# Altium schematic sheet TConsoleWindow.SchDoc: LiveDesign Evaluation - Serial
size A3; Organization: Altium Limited; Address1: L3, 12a Rodborough Rd; Address2: Frenchs Forest; Address3: NSW; Address4: Australia 2086; DocumentNumber: 4; SheetNumber: 4; SheetTotal: 7
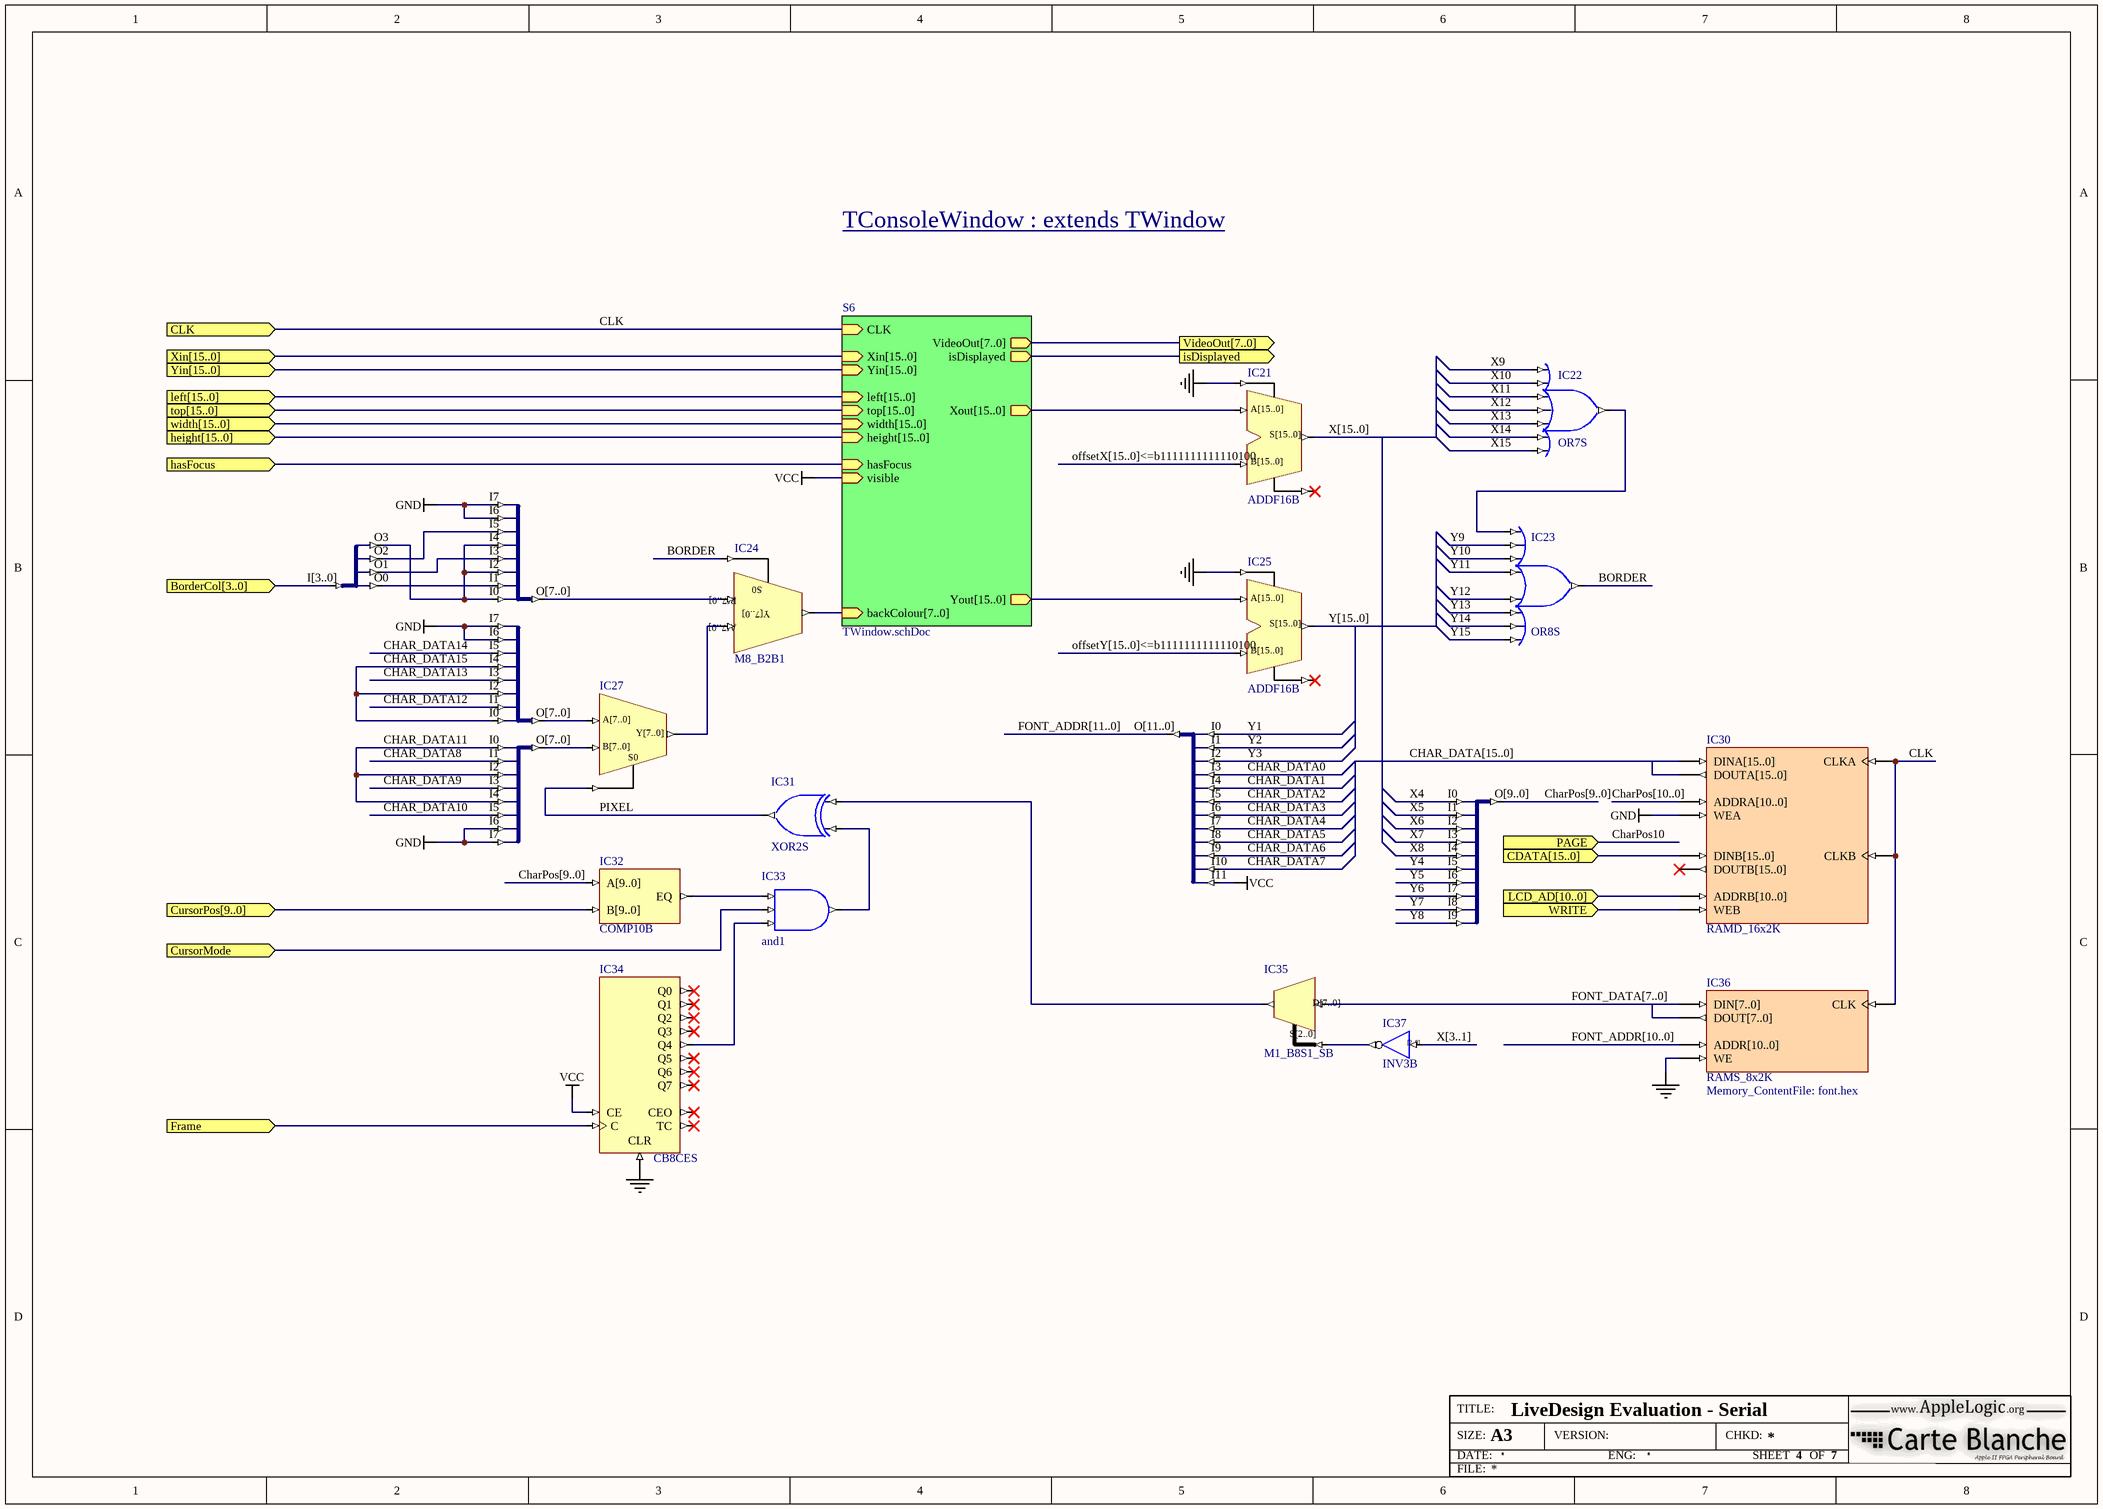
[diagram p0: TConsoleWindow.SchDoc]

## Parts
IC21  ADDF16B
IC22  OR7S
IC23  OR8S
IC24  M8_B2B1
IC25  ADDF16B
IC26  J8S_8B  (value not drawn)
IC27  M8_B2B1  (value not drawn)
IC28  J8S_8B  (value not drawn)
IC29  J8S_8B  (value not drawn)
IC30  RAMD_16x2K
IC31  XOR2S
IC32  COMP10B
IC33  and1
IC34  CB8CES
IC35  M1_B8S1_SB
IC36  RAMS_8x2K  Memory_ContentFile: font.hex
IC37  INV3B
U21  J4B_4S  (value not drawn)
U24  J10S_10B  (value not drawn)
U27  J12S_12B  (value not drawn)

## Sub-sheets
S6 = TWindow.schDoc: CLK (in), VideoOut[7..0] (out), Xin[15..0] (in), Yin[15..0] (in), top[15..0] (in), width[15..0] (in), height[15..0] (in), left[15..0] (in), Xout[15..0] (out), Yout[15..0] (out), backColour[7..0] (in), isDisplayed (out), visible (in), hasFocus (in)

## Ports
BorderCol[3..0] (in), CDATA[15..0] (in), CLK (in), CursorMode (in), CursorPos[9..0] (in), Frame (in), hasFocus (in), height[15..0] (in), isDisplayed (out), LCD_AD[10..0] (in), left[15..0] (in), PAGE (in), top[15..0] (in), VideoOut[7..0] (out), width[15..0] (in), WRITE (in), Xin[15..0] (in), Yin[15..0] (in)

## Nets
GND: IC21.CI IC25.CI IC26.I6 IC26.I7 IC28.I6 IC28.I7 IC29.I6 IC29.I7 IC30.WEA IC34.CLR IC36.WE
VCC: IC34.CE U27.I11 ; sheet S6/visible
BORDER: IC23.O IC24.S0
CHAR_DATA0: U27.I3
CHAR_DATA1: U27.I4
CHAR_DATA2: U27.I5
CHAR_DATA3: U27.I6
CHAR_DATA4: U27.I7
CHAR_DATA5: U27.I8
CHAR_DATA6: U27.I9
CHAR_DATA7: U27.I10
CHAR_DATA8: IC29.I1
CHAR_DATA9: IC29.I3
CHAR_DATA10: IC29.I5
CHAR_DATA11: IC29.I0 IC29.I2 IC29.I4
CHAR_DATA12: IC28.I1
CHAR_DATA13: IC28.I3
CHAR_DATA14: IC28.I5
CHAR_DATA15: IC28.I0 IC28.I2 IC28.I4
CLK: IC30.CLKA IC30.CLKB IC36.CLK ; port CLK, sheet S6/CLK
CursorMode: IC33.I1 ; port CursorMode
Frame: IC34.C ; port Frame
hasFocus: port hasFocus, sheet S6/hasFocus
isDisplayed: port isDisplayed, sheet S6/isDisplayed
PIXEL: IC27.S0 IC31.O
WRITE: IC30.WEB ; port WRITE
X4: U24.I0
X5: U24.I1
X6: U24.I2
X7: U24.I3
X8: U24.I4
X9: IC22.I0
X10: IC22.I1
X11: IC22.I2
X12: IC22.I3
X13: IC22.I4
X14: IC22.I5
X15: IC22.I6
Y1: U27.I0
Y2: U27.I1
Y3: U27.I2
Y4: U24.I5
Y5: U24.I6
Y6: U24.I7
Y7: U24.I8
Y8: U24.I9
Y9: IC23.I1
Y10: IC23.I2
Y11: IC23.I3
Y12: IC23.I4
Y13: IC23.I5
Y14: IC23.I6
Y15: IC23.I7
NetIC22_O: IC22.O IC23.I0
NetIC26_I0: IC26.I0 IC26.I2 IC26.I4 U21.O3
NetIC26_I1: IC26.I1 U21.O0
NetIC26_I3: IC26.I3 U21.O1
NetIC26_I5: IC26.I5 U21.O2
NetIC31_I0: IC31.I0 IC35.O
NetIC31_I1: IC31.I1 IC33.O
NetIC32_EQ: IC32.EQ IC33.I0
NetIC33_I2: IC33.I2 IC34.Q4

Not connected (* = marked no-connect by the designer): IC21 A[15..0] B[15..0] CO* S[15..0]; IC24 A[7..0] B[7..0] Y[7..0]; IC25 A[15..0] B[15..0] CO* S[15..0]; IC26 O[7..0]; IC27 A[7..0] B[7..0] Y[7..0]; IC28 O[7..0]; IC29 O[7..0]; IC30 ADDRA[10..0] ADDRB[10..0] DINA[15..0] DINB[15..0] DOUTA[15..0] DOUTB[15..0]*; IC32 A[9..0] B[9..0]; IC34 CEO* Q0* Q1* Q2* Q3* Q5* Q6* Q7* TC*; IC35 D[7..0] S[2..0]; IC36 ADDR[10..0] DIN[7..0] DOUT[7..0]; IC37 I[2..0] O[2..0]; U21 I[3..0]; U24 O[9..0]; U27 O[11..0]

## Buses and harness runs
bus CHAR_DATA[15..0]
bus CharPos[9..0]
bus CharPos[10..0]
bus FONT_ADDR[10..0]
bus FONT_ADDR[11..0]
bus FONT_DATA[7..0]
bus offsetX[15..0]<=b1111111111110100
bus offsetY[15..0]<=b1111111111110100
bus port height[15..0] = sheet S6/height[15..0]
bus port left[15..0] = sheet S6/left[15..0]
bus port top[15..0] = sheet S6/top[15..0]
bus port VideoOut[7..0] = sheet S6/VideoOut[7..0]
bus port width[15..0] = sheet S6/width[15..0]
bus port Xin[15..0] = sheet S6/Xin[15..0]
bus port Yin[15..0] = sheet S6/Yin[15..0]
bus X[3..1]
bus X[15..0]
bus Y[15..0]

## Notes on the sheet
- TConsoleWindow : extends TWindow

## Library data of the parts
IC21 IC25 = ADDF16B: 16-Bit Cascadable Unsigned Binary Full Adder, Bus Version; ArchiveName: GENERIC; VHDLIB_SIM: GENERIC_LIB
IC22 = OR7S: 7-Input OR Gate, Single Pin Version; Xilinx Equivalent: OR7; ArchiveName: GENERIC; VHDLIB_SIM: GENERIC_LIB
IC23 = OR8S: 8-Input OR Gate, Single Pin Version; ArchiveName: GENERIC; VHDLIB_SIM: GENERIC_LIB; Xilinx Equivalent: OR8
IC24 IC27 = M8_B2B1: 2x8-Bit Bus to 1x8-Bit Bus Multiplexer; ArchiveName: GENERIC; VHDLIB_SIM: GENERIC_LIB
IC26 IC28 IC29 = J8S_8B: 8 Single pin inputs to single 8-Bit output bus; ArchiveName: GENERIC; VHDLIB_SIM: GENERIC_LIB
IC30 = RAMD_16x2K: Dual Port RAM; Memory_DepthA: 2048; Memory_Type: RAM_DualPortBlock; Memory_WidthA: 16; Memory_ClockEdge: Rising; Nexus_Core: Memory_Program; Memory_EnablePin: False
IC31 = XOR2S: 2-Input Exclusive-OR Gate, Single Pin Version; ArchiveName: GENERIC; VHDLIB_SIM: GENERIC_LIB; Xilinx Equivalent: XOR2
IC32 = COMP10B: 10-Bit Identity Comparator, Bus Version; ArchiveName: GENERIC; VHDLIB_SIM: GENERIC_LIB
IC33 = AND3S: 3-Input AND Gate, Single Pin Version; ArchiveName: GENERIC; VHDLIB_SIM: GENERIC_LIB; Xilinx Equivalent: AND3
IC34 = CB8CES: 8-Bit Cascadable Binary Counters with Clock Enable and Asynchronous Clear, Single Pin Version; ArchiveName: GENERIC; VHDLIB_SIM: GENERIC_LIB
IC35 = M1_B8S1_SB: 1x8-Bit Bus to 1x1-Single Wire Multiplexer With Bus Version Select; ArchiveName: GENERIC; VHDLIB_SIM: GENERIC_LIB
IC36 = RAMS_8x2K: Single Port RAM; Memory_Type: RAM_SinglePortBlock; Memory_ClockEdge: Rising; Nexus_Core: Memory_Program; Memory_Depth: 2048; Memory_Width: 8; Memory_EnablePin: False
IC37 = INV3B: 3-Bit Inverter, Bus Version; ArchiveName: GENERIC; VHDLIB_SIM: GENERIC_LIB
U21 = J4B_4S: 4-Bit input bus to 4 Single pin outputs; ArchiveName: GENERIC; VHDLIB_SIM: GENERIC_LIB
U24 = J10S_10B: 10 Single pin inputs to single 10-Bit output bus; ArchiveName: GENERIC; VHDLIB_SIM: GENERIC_LIB
U27 = J12S_12B: 12 Single pin inputs to single 12-Bit output bus; ArchiveName: GENERIC; VHDLIB_SIM: GENERIC_LIB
